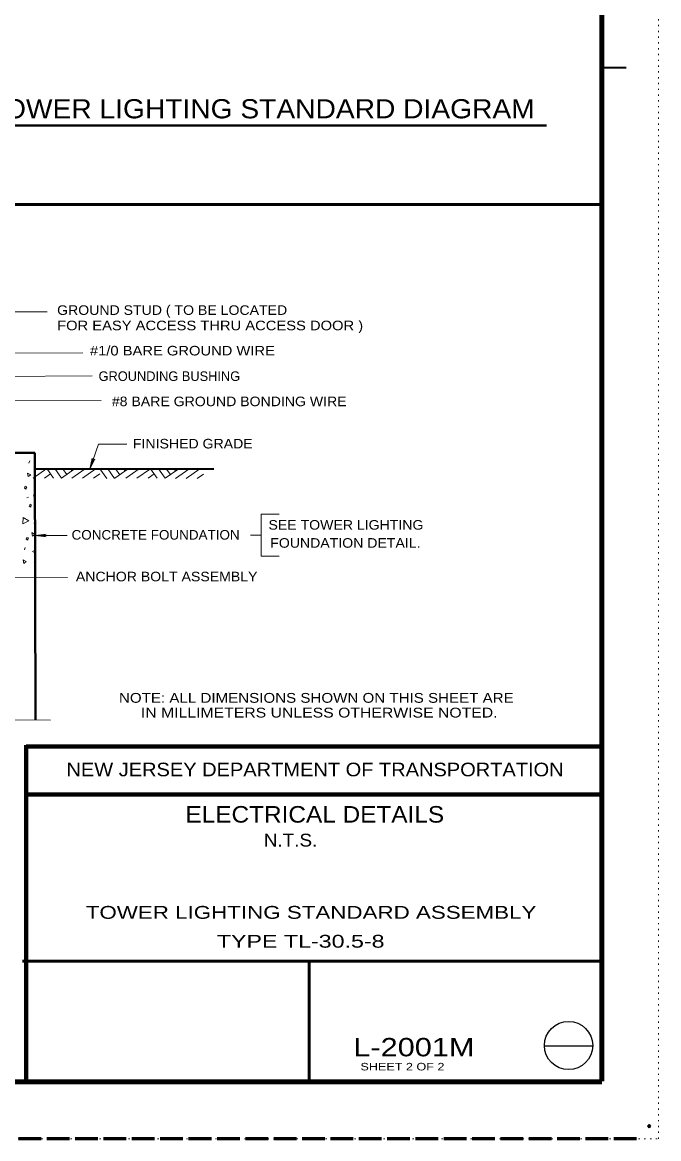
# Model space of a CAD drawing. Extents: x 312583 to 312854, y 144419 to 144597.
# Drawn here: x 312803 to 312853.5, y 144418.6 to 144507.2 of the extents above; entities that cross this region are included whole.
import ezdxf
from ezdxf.enums import TextEntityAlignment as Align

# ---------------------------------------------------------------- set-up
doc = ezdxf.new("R2010")
doc.units = 0
doc.header["$LTSCALE"] = 0.3
doc.header["$PDMODE"] = 32
doc.header["$PDSIZE"] = 0.15
doc.linetypes.add('DOTTED', pattern=[1.5, 0.3, -1.2])
doc.linetypes.add('LONG_DASHED', pattern=[7.5, 6, -1.5])
for name, color, linetype, lineweight in [('1', 7, 'Continuous', 40), ('10', 7, 'Continuous', 25), ('2', 7, 'Continuous', 13), ('62', 7, 'DOTTED', 13), ('63', 7, 'LONG_DASHED', 60)]:
    doc.layers.add(name, color=color, linetype=linetype, lineweight=lineweight)
doc.layers.add('5', color=7, linetype='Continuous')

msp = doc.modelspace()

# ---------------------------------------------------------------- linework, layer by layer
at = {"layer": '1', "lineweight": 158}
for p, q in [((312849, 144423.1446), (312849, 144585.0846)), ((312616.5, 144423.0846), (312849, 144423.0846))]:
    msp.add_line(p, q, dxfattribs=at)
at = {"layer": '1', "lineweight": 35}
msp.add_line((312849, 144503.6216), (312850.932, 144503.6216), dxfattribs=at)
at = {"layer": '1'}
for p, q in [((312787.4365, 144472.9926), (312803.9888, 144473.0309)), ((312818.1952, 144471.7659), (312803.9888, 144471.7429))]:
    msp.add_line(p, q, dxfattribs=at)
at = {"layer": '1', "lineweight": 80}
for p, q in [((312803.31, 144423.1446), (312803.31, 144449.8146)), ((312803.31, 144449.7246), (312849, 144449.7246)), ((312803.31, 144445.9146), (312849, 144445.9146))]:
    msp.add_line(p, q, dxfattribs=at)
at = {"layer": '1', "lineweight": 53}
for p, q in [((312849, 144432.6666), (312803, 144432.6666)), ((312825.7546, 144432.6666), (312825.7546, 144423.1446))]:
    msp.add_line(p, q, dxfattribs=at)
at = {"layer": '1'}
msp.add_point((312852.75, 144419.5846), dxfattribs=at)
at = {"layer": '10'}
msp.add_line((312844.4383, 144425.966), (312848.2793, 144425.966), dxfattribs=at)
msp.add_circle((312846.3494, 144425.9805), 1.9159, dxfattribs=at)
at = {"layer": '2', "lineweight": 40}
for p, q in [((312789.8216, 144499.0172), (312844.6106, 144499.0172)), ((312804.0348, 144451.8172), (312803.9888, 144473.0309))]:
    msp.add_line(p, q, dxfattribs=at)
at = {"layer": '2', "lineweight": 53}
msp.add_line((312688.002, 144492.7581), (312849.0076, 144492.7581), dxfattribs=at)
at = {"layer": '2'}
for p, q in [((312795.7012, 144484.1936), (312804.9778, 144484.2319)), ((312797.1118, 144480.9199), (312807.7992, 144480.9659)), ((312800.3395, 144479.1029), (312808.5505, 144479.1412)), ((312798.9365, 144477.2169), (312809.2482, 144477.1786)), ((312809.0565, 144473.7209), (312808.3665, 144471.7506)), ((312809.0565, 144473.7209), (312811.3028, 144473.7286)), ((312803.5902, 144472.3946), (312803.5058, 144472.2259)), ((312808.3665, 144471.7506), (312808.5505, 144472.6016)), ((312808.3665, 144471.7506), (312808.7575, 144472.5326)), ((312808.5505, 144472.6016), (312808.5582, 144472.3102)), ((312808.7575, 144472.5326), (312808.5582, 144472.3102)), ((312803.8662, 144471.0299), (312804.9395, 144471.7889)), ((312804.7478, 144471.0299), (312805.2385, 144471.3749)), ((312804.9395, 144471.7889), (312805.4838, 144471.0299)), ((312805.5682, 144471.7889), (312806.1048, 144471.0299)), ((312806.1048, 144471.0299), (312807.1935, 144471.7889)), ((312806.1892, 144471.7889), (312806.5265, 144471.3136)), ((312806.8178, 144471.7812), (312806.9405, 144471.6126)), ((312806.9405, 144471.0222), (312807.9755, 144471.7582)), ((312807.7838, 144471.0222), (312808.8495, 144471.7812)), ((312808.6578, 144471.0222), (312809.1485, 144471.3672)), ((312809.1485, 144471.7736), (312809.6928, 144471.0069)), ((312809.7772, 144471.7736), (312810.3215, 144471.0069)), ((312810.3368, 144471.0222), (312811.4025, 144471.7736)), ((312810.4058, 144471.7736), (312810.7355, 144471.2982)), ((312811.0345, 144471.7659), (312811.1495, 144471.5972)), ((312811.2185, 144471.0146), (312812.2842, 144471.7736)), ((312812.0925, 144471.0146), (312813.1658, 144471.7736)), ((312812.9742, 144471.0146), (312813.4648, 144471.3596)), ((312813.1658, 144471.7736), (312813.7102, 144471.0146)), ((312813.7945, 144471.7736), (312814.3312, 144471.0146)), ((312814.3312, 144471.0146), (312815.4198, 144471.7736)), ((312814.4155, 144471.7736), (312814.7528, 144471.3059)), ((312815.0442, 144471.7736), (312815.1668, 144471.5972)), ((312815.1668, 144471.0069), (312816.2018, 144471.7429)), ((312816.0102, 144471.0069), (312817.0758, 144471.7659)), ((312816.8842, 144471.0069), (312817.3748, 144471.3519)), ((312803.3448, 144469.4736), (312803.4828, 144469.5119)), ((312803.8968, 144469.7112), (312803.9275, 144469.4966)), ((312821.9429, 144468.1779), (312821.9429, 144464.8276)), ((312821.9429, 144468.1779), (312823.3843, 144468.1779)), ((312803.9122, 144467.4572), (312803.9888, 144467.4342)), ((312804.0118, 144466.4759), (312804.8782, 144466.5832)), ((312804.0118, 144466.4759), (312806.5648, 144466.4836)), ((312804.0118, 144466.4759), (312804.8782, 144466.3686)), ((312804.8782, 144466.5832), (312804.6022, 144466.4759)), ((312804.8782, 144466.3686), (312804.6022, 144466.4759)), ((312821.9429, 144466.5066), (312821.0996, 144466.5066)), ((312803.2375, 144465.5099), (312803.1608, 144465.3412)), ((312803.9428, 144464.3216), (312804.0042, 144464.2449)), ((312821.9429, 144464.8276), (312823.3843, 144464.8276)), ((312801.2442, 144463.1179), (312806.5725, 144463.1256)), ((312797.5105, 144451.8632), (312805.2232, 144451.8019))]:
    msp.add_line(p, q, dxfattribs=at)
for points in [[(312803.7052, 144473.0232), (312803.7895, 144472.9849), (312803.7895, 144473.0232)], [(312804.0042, 144465.2952), (312803.8125, 144465.1956), (312804.0042, 144465.0882)]]:
    msp.add_lwpolyline(points, dxfattribs=at)
for points in [[(312803.4675, 144471.1449), (312803.6668, 144471.2829), (312803.4215, 144471.4286)], [(312803.2988, 144470.2632), (312803.3448, 144470.3399), (312803.2298, 144470.3782), (312803.1685, 144470.2326), (312803.2988, 144470.1559)], [(312803.6822, 144468.8449), (312803.7205, 144468.9139), (312803.6132, 144468.9522), (312803.5518, 144468.8066), (312803.6822, 144468.7299)], [(312803.0535, 144467.9096), (312803.0458, 144467.3959), (312803.5212, 144467.6259)], [(312803.7972, 144466.4069), (312803.9965, 144466.5526), (312803.7588, 144466.6982)], [(312803.4445, 144466.2076), (312803.4828, 144466.2842), (312803.3678, 144466.3226), (312803.3142, 144466.1692), (312803.4445, 144466.1002)], [(312803.1225, 144464.2602), (312803.3142, 144464.3982), (312803.0765, 144464.5439)]]:
    msp.add_lwpolyline(points, close=True, dxfattribs=at)
at = {"layer": '62'}
msp.add_lwpolyline([(312601.2, 144418.5846), (312853.5, 144418.5846), (312853.5, 144596.7846)], dxfattribs=at)
at = {"layer": '63'}
msp.add_line((312851.75, 144418.5846), (312583.526, 144418.5846), dxfattribs=at)

# ---------------------------------------------------------------- texts
at = {"layer": '1'}
for s, height, width, p in [('NOTE: ALL DIMENSIONS SHOWN ON THIS SHEET ARE', 0.78, 1.15, (312810.6706, 144453.1904)), ('     IN MILLIMETERS UNLESS OTHERWISE NOTED.', 0.78, 1.2, (312810.6705, 144452.0204)), ('SHEET 2 OF 2', 0.598, 1.25, (312829.8333, 144424.0033))]:
    msp.add_text(s, height=height, dxfattribs=dict(at, width=width)).set_placement(p)
at = {"layer": '1', "width": 1.1}
for s, height, p in [('NEW JERSEY DEPARTMENT OF TRANSPORTATION', 1.08, (312826.2285, 144447.3546)), ('ELECTRICAL DETAILS', 1.315, (312826.2107, 144443.676))]:
    msp.add_text(s, height=height, dxfattribs=at).set_placement(p, align=Align.CENTER)
at = {"layer": '2'}
for s, height, width, p in [('TYPICAL TOWER LIGHTING STANDARD DIAGRAM', 1.52, 1.1, (312816.9509, 144499.5905)), ('    N.T.S.  ', 1.02, 1.1, (312823.87, 144441.778)), ('      TOWER LIGHTING STANDARD ASSEMBLY      ', 1.02, 1.3, (312825.9156, 144436.04)), ('                TYPE TL-30.5-8               ', 1.02, 1.35, (312824.8356, 144433.7476))]:
    msp.add_text(s, height=height, dxfattribs=dict(at, width=width)).set_placement(p, align=Align.CENTER)
for s, width, p in [('GROUND STUD ( TO BE LOCATED', 1.1, (312805.7598, 144483.9856)), ('FOR EASY ACCESS THRU ACCESS DOOR )', 1.15, (312805.7598, 144482.7656)), ('#1/0 BARE GROUND WIRE', 1.15, (312808.3654, 144480.7656)), ('#8 BARE GROUND BONDING WIRE', 1.1, (312810.1024, 144476.7371)), ('FINISHED GRADE', 1.1, (312811.7761, 144473.3826)), ('SEE TOWER LIGHTING', 1.1, (312822.5333, 144466.9349)), ('CONCRETE FOUNDATION', 1.05, (312806.9077, 144466.1452)), ('FOUNDATION DETAIL.', 1.1, (312822.6734, 144465.5012)), ('ANCHOR BOLT ASSEMBLY', 1.1, (312807.2493, 144462.8332))]:
    msp.add_text(s, height=0.76, dxfattribs=dict(at, width=width)).set_placement(p)
msp.add_text('GROUNDING BUSHING', height=0.76, dxfattribs=at).set_placement((312809.0512, 144478.7409))
at = {"layer": '5', "width": 1.25}
msp.add_text('L-2001M   ', height=1.457, dxfattribs=at).set_placement((312835.0904, 144425.1226), align=Align.CENTER)

doc.saveas('drawing.dxf')
